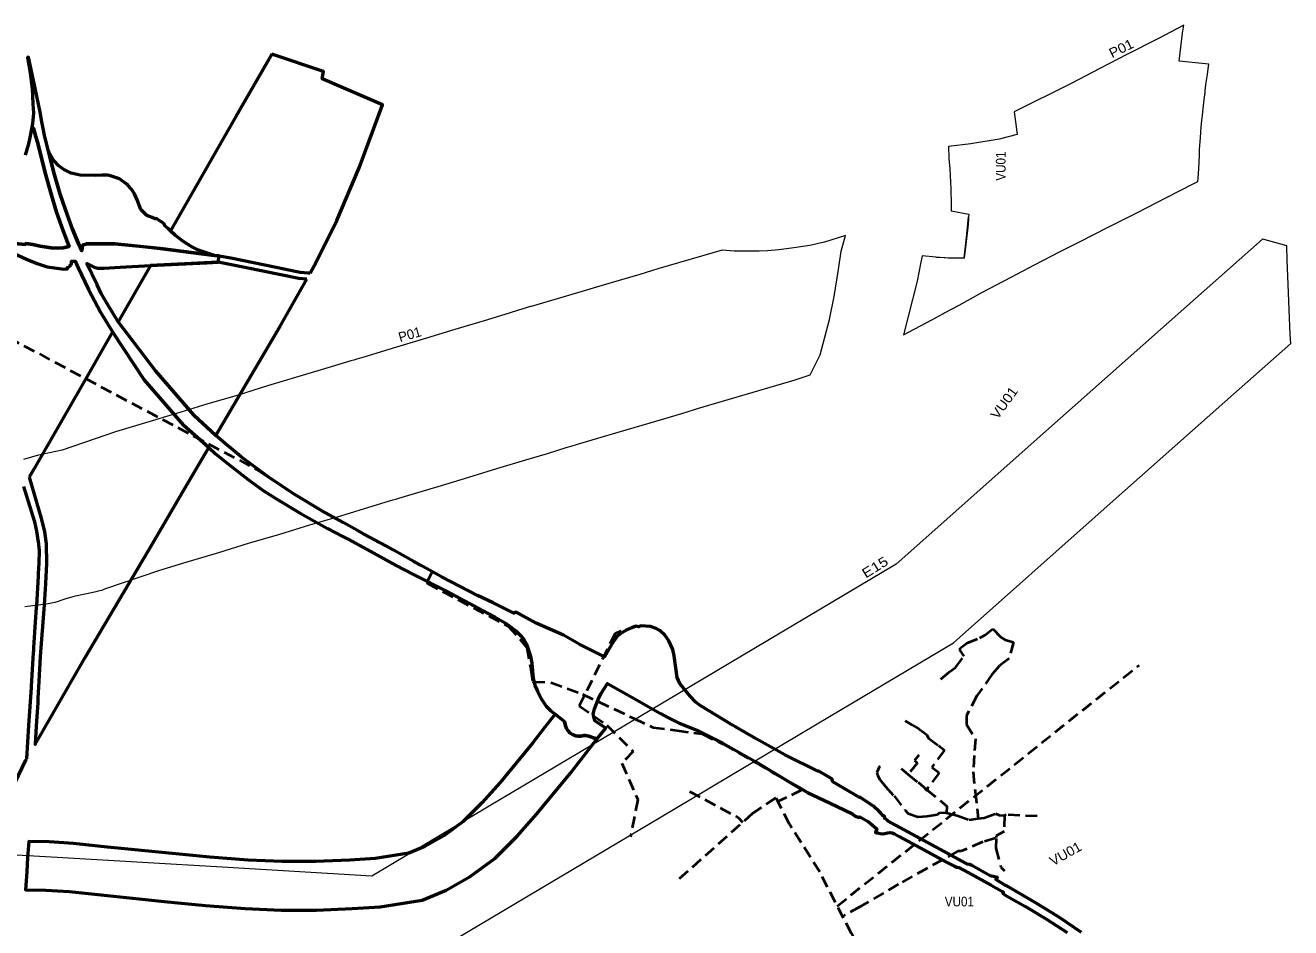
# Model space of a CAD drawing. Extents: x -650145 to -642675, y -1074338 to -1066803.
# Drawn here: x -647799 to -645184, y -1069131 to -1067267 of the extents above; entities that cross this region are included whole.
import ezdxf

# ---------------------------------------------------------------- set-up
doc = ezdxf.new("R2010")
doc.units = 0
doc.header["$LTSCALE"] = 8
doc.header["$PDMODE"] = 32
doc.header["$PDSIZE"] = 4
doc.linetypes.add('MEDIUM_DASHED', pattern=[4.5, 3, -1.5])
for name, color, linetype, lineweight in [('12', 7, 'MEDIUM_DASHED', 40), ('13', 7, 'MEDIUM_DASHED', 40), ('15', 7, 'Continuous', 13), ('20', 7, 'Continuous', 13), ('44', 7, 'Continuous', 53), ('45', 7, 'Continuous', 53)]:
    doc.layers.add(name, color=color, linetype=linetype, lineweight=lineweight)
for name, color, linetype in [('17', 7, 'Continuous'), ('2', 7, 'Continuous'), ('7', 7, 'Continuous')]:
    doc.layers.add(name, color=color, linetype=linetype)

msp = doc.modelspace()

# ---------------------------------------------------------------- linework, layer by layer
at = {"layer": '12'}
msp.add_line((-646121.289, -1069086.031), (-645497.437, -1068588.325), dxfattribs=at)
for points in [[(-646567.712, -1068518.211), (-646580.293, -1068523.244), (-646654.473, -1068672.619), (-646597.568, -1068712.249), (-646542.696, -1068767.122), (-646566.575, -1068791.001), (-646533.55, -1068865.689), (-646548.767, -1068942.794)], [(-646062.183, -1069574.695), (-646024.736, -1069561.612), (-645973.562, -1069340.254), (-646092.013, -1069143.037), (-646157.557, -1069015.41), (-646220.085, -1068916.892), (-646248.016, -1068862.258), (-646295.932, -1068894.5), (-646451.322, -1069032.874)], [(-646426.669, -1068849.138), (-646325.196, -1068903.916), (-646316.818, -1068913.099)]]:
    msp.add_lwpolyline(points, dxfattribs=at)
at = {"layer": '13'}
msp.add_line((-645981.259, -1068703.512), (-645967.385, -1068711.482), dxfattribs=at)
for points in [[(-648215.035, -1067709.37), (-647316.251, -1068186.868), (-647259.835, -1068225.099), (-647186.21, -1068269.45), (-646980.7, -1068383.53), (-646959.293, -1068395.4), (-646959.185, -1068396.415), (-646969.622, -1068417.689), (-646968.614, -1068419.427), (-646801.035, -1068508.24), (-646762.42, -1068551.731), (-646754.632, -1068597.002), (-646750.967, -1068622.409), (-646749.448, -1068623.2), (-646712.965, -1068624.297), (-646647.976, -1068648.366), (-646541.222, -1068698.652), (-646502.045, -1068716.94), (-646453.105, -1068723.49), (-646400.555, -1068730.38)], [(-645907.362, -1068617.782), (-645889.568, -1068602.563), (-645876.887, -1068593.676), (-645859.253, -1068569.608), (-645867.265, -1068558.084), (-645867.406, -1068553.24), (-645853.323, -1068543.361), (-645827.027, -1068531.945), (-645816.331, -1068526.326), (-645800.023, -1068513.497), (-645783.355, -1068530.492), (-645774.539, -1068535.947), (-645757.012, -1068540.689), (-645766.363, -1068574.93), (-645786.158, -1068590.096), (-645800.925, -1068607.466), (-645832.749, -1068651.725), (-645854.306, -1068692.564), (-645854.5, -1068711.115), (-645835.59, -1068740.909), (-645838.212, -1068775.032), (-645840.834, -1068809.155), (-645836.304, -1068849.486), (-645830.009, -1068905.531), (-645817.671, -1068904.145), (-645794.595, -1068895.246), (-645786.942, -1068898.462), (-645775.928, -1068898.705), (-645776.729, -1068932.361), (-645793.148, -1068940.923), (-645793.235, -1068944.604)], [(-646400.555, -1068730.38), (-646357.387, -1068751.896), (-646289.907, -1068789.892), (-646249.623, -1068813.511), (-646193.945, -1068846.371), (-646243.837, -1068870.431)], [(-645967.385, -1068711.482), (-645952.849, -1068719.994), (-645936.763, -1068731.758), (-645932.629, -1068739.558), (-645912.463, -1068754.396), (-645899.435, -1068764.348), (-645926.111, -1068799.268), (-645910.63, -1068811.261), (-645936.673, -1068845.097)], [(-645953.001, -1068774.241), (-645961.611, -1068785.748), (-645955.699, -1068790.171), (-645974.573, -1068814.129)], [(-646035.717, -1068796.972), (-646034.272, -1068798.019), (-646039.344, -1068810.269), (-646038.415, -1068815.963), (-646033.439, -1068824.717), (-646021.705, -1068839.115), (-646003.913, -1068858.499), (-645981.578, -1068887.109), (-645974.499, -1068895.164), (-645955.122, -1068901.554), (-645935.448, -1068900.633), (-645914.39, -1068896.88), (-645909.484, -1068892.742), (-645895.621, -1068893.663), (-645895.62, -1068893.657), (-645873.598, -1068899.269), (-645848.914, -1068907.655), (-645830.009, -1068905.531)], [(-645989.584, -1068801.939), (-645974.573, -1068814.129), (-645954.496, -1068830.434), (-645936.673, -1068845.097)], [(-645936.673, -1068845.097), (-645894.69, -1068879.637), (-645895.621, -1068893.657)], [(-645708.174, -1068900.605), (-645772.413, -1068897.59), (-645775.928, -1068898.705)], [(-645794.219, -1068945.883), (-645820.762, -1068953.606), (-645865.144, -1068972.751), (-645871.883, -1068972.89), (-645994.94, -1069041.005), (-646073.429, -1069086.912), (-646109.842, -1069107.217)], [(-645793.282, -1068946.603), (-645793.758, -1068966.676), (-645783.039, -1069005.778), (-645775.966, -1069013.04)]]:
    msp.add_lwpolyline(points, dxfattribs=at)
msp.add_point((-645936.673, -1068845.097), dxfattribs=at)
at = {"layer": '15'}
for points in [[(-645405.461, -1067266.956), (-645459.124, -1067294.842), (-645523.1, -1067327.464), (-645578.654, -1067356.15), (-645636.938, -1067386.16), (-645755.627, -1067445.619), (-645754.45, -1067456.07), (-645749.67, -1067492.54), (-645786.52, -1067502.4), (-645845.49, -1067511.66), (-645891.61, -1067517.46), (-645890.8, -1067542.09), (-645888.69, -1067563.35), (-645886.5, -1067604.41), (-645886.3, -1067638)], [(-645353.76, -1067347.31), (-645381.01, -1067344.47), (-645414.55, -1067340.98), (-645412.77, -1067323.6), (-645407.69, -1067283.25), (-645405.461, -1067266.956)], [(-645360.9, -1067401.05), (-645358.77, -1067385.3), (-645356.48, -1067368.37), (-645354.97, -1067357.16), (-645353.76, -1067347.31)], [(-645366.91, -1067452.72), (-645363.1, -1067419.95), (-645361.48, -1067406.06), (-645360.9, -1067401.05)], [(-645369.16, -1067476.7), (-645367.93, -1067463.58), (-645366.91, -1067452.72)], [(-645371.73, -1067507.06), (-645371.09, -1067499.49), (-645369.16, -1067476.7)], [(-645374.09, -1067562.75), (-645373, -1067535.51), (-645372.51, -1067523.27), (-645371.73, -1067507.06)], [(-645376.157, -1067589.286), (-645375.63, -1067582.48), (-645374.09, -1067562.75)], [(-645984.712, -1067905.99), (-645926.226, -1067874.994), (-645903.512, -1067862.929), (-645901.047, -1067861.609), (-645900.008, -1067861.056), (-645869.73, -1067844.967), (-645822.534, -1067819.103), (-645761.702, -1067787.243), (-645713.714, -1067761.995), (-645660.64, -1067734.415), (-645619.713, -1067713.557), (-645563.205, -1067684.762), (-645501.082, -1067653.64), (-645441.166, -1067622.79), (-645386.14, -1067594.376), (-645376.157, -1067589.286)], [(-645886.3, -1067638), (-645886.24, -1067648.47), (-645886.23, -1067649.44), (-645886.23, -1067649.94), (-645849.48, -1067657.36), (-645849.52, -1067657.86), (-645849.92, -1067662.49)], [(-645849.92, -1067662.49), (-645850.48, -1067668.94), (-645851.81, -1067684.35), (-645858.82, -1067747.99), (-645892.22, -1067747.76), (-645917.73, -1067746.17), (-645946.03, -1067743.35), (-645949.27, -1067759.64), (-645955.97, -1067795.26), (-645984.712, -1067905.99)], [(-645917.73, -1067746.17), (-645858.82, -1067747.99), (-645853.346, -1067698.291), (-645849.92, -1067662.49)], [(-646137.4, -1067874.3), (-646127.7, -1067827.4), (-646118.8, -1067771.3), (-646113, -1067733.4), (-646104.6, -1067701), (-646147.4, -1067714.8), (-646177.7, -1067721.6), (-646215.6, -1067727), (-646241.8, -1067731), (-646265.3, -1067733), (-646282.66, -1067733.1), (-646334.1, -1067733.4), (-646359.237, -1067731.258), (-646492.002, -1067769.967)], [(-646492.002, -1067769.967), (-646504.961, -1067774.022), (-646529.365, -1067781.499), (-646593.13, -1067800.524), (-646658.06, -1067819.479), (-646742.053, -1067843.994), (-646753.887, -1067847.445), (-646755.382, -1067847.819), (-646771.25, -1067852.794), (-646807.854, -1067864.206), (-646850.892, -1067877.156), (-646911.586, -1067895.218), (-646969.855, -1067913.144), (-647032.093, -1067931.929), (-647048.173, -1067936.726), (-647099.576, -1067952.077), (-647114.132, -1067956.487), (-647120.451, -1067958.402), (-647126.241, -1067960.149), (-647166.751, -1067972.422), (-647233.528, -1067992.581), (-647298.314, -1068011.911), (-647358.997, -1068030.632), (-647423.612, -1068049.375), (-647486.376, -1068068.781), (-647550.936, -1068088.002), (-647612.779, -1068106.747), (-647722.769, -1068144.312), (-647762.416, -1068152.578), (-647765.408, -1068153.202), (-647771.336, -1068154.692), (-647774.267, -1068155.557), (-647802.757, -1068163.967)], [(-646409.773, -1068058.581), (-646208.581, -1067999.266), (-646177.649, -1067988.892), (-646156.3, -1067947.3), (-646137.4, -1067874.3)], [(-647799.757, -1068467.7), (-647755.597, -1068461.87), (-647751.962, -1068461.39), (-647744.747, -1068460.076), (-647737.604, -1068458.41), (-647730.552, -1068456.398), (-647727.079, -1068455.221), (-647712.829, -1068450.391), (-647710.163, -1068449.487), (-647709.521, -1068449.242), (-647695.198, -1068445.014), (-647652.454, -1068436.102), (-647647.917, -1068435.156), (-647638.976, -1068432.708), (-647634.59, -1068431.21), (-647520.761, -1068392.333), (-647464.624, -1068375.318), (-647399.264, -1068355.859), (-647337.508, -1068336.765), (-647272.983, -1068318.048), (-647211.206, -1068298.989), (-647147.292, -1068279.919), (-647079.909, -1068259.578), (-647039.419, -1068247.311), (-647033.609, -1068245.558), (-647027.128, -1068243.593), (-647013.164, -1068239.363), (-646962.367, -1068224.194), (-646945.867, -1068219.271), (-646882.405, -1068200.116), (-646824.694, -1068182.362), (-646764.888, -1068164.564), (-646719.986, -1068151.054), (-646681.73, -1068139.126), (-646671.337, -1068135.868), (-646658.027, -1068131.986), (-646574, -1068107.461), (-646508.21, -1068088.256), (-646442.535, -1068068.661), (-646416.219, -1068060.598), (-646409.773, -1068058.581)]]:
    msp.add_lwpolyline(points, dxfattribs=at)
at = {"layer": '20'}
for points in [[(-646738.287, -1069051.902), (-646456.362, -1068884.319), (-646162.737, -1068709.771), (-645881.136, -1068542.25), (-645563.458, -1068260.279), (-645320.624, -1068044.744), (-645184.426, -1067923.894), (-645185.5, -1067905.76), (-645190.61, -1067785.41), (-645191.55, -1067752.42), (-645192.4, -1067722.74), (-645241.99, -1067708.63), (-645242.878, -1067708.378)], [(-645242.878, -1067708.378), (-645453.376, -1067895.156), (-645696.222, -1068110.701)], [(-645696.222, -1068110.701), (-645999.704, -1068380.07), (-646264.963, -1068537.869), (-646558.558, -1068712.401), (-646840.473, -1068879.978), (-647082.853, -1069024.029), (-647392.269, -1069006.02), (-647721.495, -1068986.72), (-648010.52, -1068969.88), (-648329.902, -1068951.251), (-648639.277, -1068933.111), (-648948.071, -1068915.071), (-649057.05, -1068908.69), (-649199.47, -1069030.73), (-649232.77, -1069060.44), (-649258.79, -1069091.17), (-649263.719, -1069096.97)], [(-649263.719, -1069096.97), (-648650.963, -1069132.769), (-648341.578, -1069150.909), (-648022.16, -1069169.54), (-647733.165, -1069186.38), (-647403.931, -1069205.68), (-647033.327, -1069227.251), (-646738.287, -1069051.902)]]:
    msp.add_lwpolyline(points, dxfattribs=at)
at = {"layer": '44'}
for points in [[(-647400.63, -1067756.19), (-647540.208, -1067762.876), (-647593.267, -1067855.425), (-647606.818, -1067879.061)], [(-647217.611, -1067791.149), (-647233.83, -1067789.69), (-647345.11, -1067767.28), (-647400.63, -1067756.19)], [(-647405.026, -1068113.904), (-647273.297, -1067889.981), (-647217.611, -1067791.149)], [(-647464.94, -1068215.752), (-647461.188, -1068209.373), (-647419.713, -1068138.871), (-647472.338, -1068093.096), (-647553.628, -1067999.427), (-647618.773, -1067899.914), (-647685.819, -1068016.861)], [(-647606.818, -1067879.061), (-647530.038, -1067980.839), (-647451.024, -1068071.886), (-647405.026, -1068113.904)], [(-647685.819, -1068016.861), (-647781.346, -1068183.485), (-647791.055, -1068200.507)], [(-647791.055, -1068200.507), (-647765.22, -1068287.94), (-647759.412, -1068313.436)], [(-647771.413, -1068334.626), (-647774.94, -1068311.47), (-647779.55, -1068292.23), (-647780.07, -1068290.53), (-647801.797, -1068219.34)], [(-647768.02, -1068570.36), (-647770.94, -1068622.47), (-647772.85, -1068656.41), (-647773.08, -1068660.57), (-647773.4, -1068665.71), (-647776.5, -1068714.8), (-647778.95, -1068752.433), (-647675.054, -1068572.919), (-647535.844, -1068336.279), (-647464.94, -1068215.752)], [(-647759.412, -1068313.436), (-647758.45, -1068317.66), (-647756.09, -1068337.61), (-647754.99, -1068378.21), (-647757.41, -1068419.98), (-647760.22, -1068463.96), (-647768.02, -1068570.36)], [(-647796.173, -1068782.191), (-647791.77, -1068713.23), (-647786.47, -1068634.37), (-647786.32, -1068632.19), (-647781.85, -1068562.97), (-647781.55, -1068558.38), (-647781.13, -1068551.88), (-647778.24, -1068499.95), (-647775.82, -1068469.74), (-647775.52, -1068464.97), (-647771.74, -1068404.5), (-647771.47, -1068400.07), (-647770.12, -1068377.5), (-647769.92, -1068352.1), (-647770.81, -1068340.29), (-647771.05, -1068337.01), (-647771.413, -1068334.626)], [(-647846.989, -1068896.545), (-647820.883, -1068832.117), (-647797.632, -1068784.713), (-647796.173, -1068782.191)]]:
    msp.add_lwpolyline(points, dxfattribs=at)
at = {"layer": '45'}
for points in [[(-647681.91, -1067732.74), (-647690.09, -1067716.05), (-647702.04, -1067686.86), (-647715.92, -1067648.12), (-647727.37, -1067614.33), (-647740.49, -1067568.67), (-647751.41, -1067526.58), (-647756.55, -1067505.32), (-647759.16, -1067494.01), (-647764.89, -1067466.64), (-647768.5, -1067446.04), (-647778.78, -1067397.1), (-647792.52, -1067332.74), (-647794.54, -1067333.14), (-647788.77, -1067365.03), (-647784.55, -1067398.01), (-647783.21, -1067429.237)], [(-647289.924, -1067326.309), (-647364.024, -1067455.561), (-647499.095, -1067691.163), (-647489.3, -1067700.07)], [(-647210.537, -1067778.594), (-647198.088, -1067756.5), (-647155.592, -1067670.17), (-647108.971, -1067561.55), (-647061.252, -1067430.908), (-647185.93, -1067377.38), (-647183.09, -1067362.16), (-647289.924, -1067326.309)], [(-647783.21, -1067429.237), (-647782.39, -1067448.34), (-647782.5, -1067455.11), (-647784.36, -1067469.6), (-647785.64, -1067477.02), (-647781.85, -1067479.19), (-647777.55, -1067496.95), (-647773.96, -1067508.48), (-647768.5, -1067529.75), (-647758.25, -1067571.79)], [(-647777.55, -1067496.95), (-647781.85, -1067479.19), (-647785.64, -1067477.02), (-647789.39, -1067498.84), (-647792.54, -1067511.85), (-647799.39, -1067535.48)], [(-647768.5, -1067529.75), (-647773.96, -1067508.48), (-647777.55, -1067496.95)], [(-647721.05, -1067691.73), (-647734.63, -1067652.57), (-647744.61, -1067617.96), (-647758.25, -1067571.79), (-647768.5, -1067529.75)], [(-647729.802, -1067557.462), (-647740.124, -1067546.265), (-647751.41, -1067526.58), (-647740.49, -1067568.67)], [(-647620.586, -1067578.478), (-647628.441, -1067576.759), (-647640.087, -1067576.306), (-647654.743, -1067576.996), (-647685.968, -1067576.68), (-647704.458, -1067572.034), (-647719.661, -1067564.884), (-647729.802, -1067557.462)], [(-647758.25, -1067571.79), (-647744.61, -1067617.96), (-647734.63, -1067652.57), (-647721.05, -1067691.73), (-647708.71, -1067723.99)], [(-647740.49, -1067568.67), (-647727.37, -1067614.33), (-647715.92, -1067648.12), (-647702.04, -1067686.86), (-647690.09, -1067716.05), (-647681.91, -1067732.74), (-647680.804, -1067720.745), (-647672, -1067718), (-647643, -1067718), (-647617.443, -1067718), (-647614, -1067718)], [(-647547.663, -1067659.519), (-647560.187, -1067647.458), (-647567.744, -1067627.24), (-647573.605, -1067614.951), (-647580.539, -1067604.432), (-647586.864, -1067597.411), (-647591.227, -1067593.613), (-647604.415, -1067584.047), (-647606.559, -1067583.309), (-647620.586, -1067578.478)], [(-647499.095, -1067691.163), (-647503.97, -1067686.73), (-647510.6, -1067680.86), (-647511.24, -1067677.53), (-647517.74, -1067672.85), (-647520.13, -1067671.13), (-647527.76, -1067665.65), (-647530.82, -1067666.65), (-647536.83, -1067663.64), (-647547.663, -1067659.519)], [(-647462.45, -1067719.84), (-647474.13, -1067711.81), (-647489.3, -1067700.07), (-647499.095, -1067691.163)], [(-647708.71, -1067723.99), (-647720.45, -1067726.49), (-647732.71, -1067727.02), (-647745.41, -1067726.6), (-647768.53, -1067722.82), (-647783.13, -1067719.68), (-647798.17, -1067717.58), (-647798.5, -1067719.67), (-647821.02, -1067717.33)], [(-647821.02, -1067717.33), (-647798.5, -1067719.67), (-647798.17, -1067717.58)], [(-647798.17, -1067717.58), (-647783.13, -1067719.68), (-647768.53, -1067722.82), (-647745.41, -1067726.6), (-647732.71, -1067727.02), (-647720.45, -1067726.49), (-647708.71, -1067723.99), (-647721.05, -1067691.73)], [(-647489.3, -1067700.07), (-647474.13, -1067711.81), (-647462.45, -1067719.84), (-647453.87, -1067724.97), (-647440.81, -1067731.38), (-647408.2, -1067742.37), (-647398.74, -1067743.15)], [(-647829.49, -1067734.58), (-647796.87, -1067750.25), (-647774.54, -1067758.68), (-647753.53, -1067765.58), (-647718.54, -1067770.6), (-647712.01, -1067769.63), (-647712.26, -1067767.28), (-647709.834, -1067766.324), (-647707.985, -1067765.133), (-647706.723, -1067763.999), (-647705.29, -1067762.21), (-647704.447, -1067760.707), (-647703.675, -1067758.576), (-647703.315, -1067756.406), (-647703.4, -1067753.8), (-647695.71, -1067753.9), (-647690.19, -1067766.37), (-647668.13, -1067812.76), (-647643.83, -1067859.13), (-647618.773, -1067899.914), (-647553.628, -1067999.427), (-647472.338, -1068093.096), (-647419.713, -1068138.871), (-647405.71, -1068151.74), (-647372.38, -1068179.01), (-647337.74, -1068205.67), (-647307.39, -1068227.44), (-647281.64, -1068244.34), (-647230.83, -1068274.93), (-647174.56, -1068306.35), (-647142.788, -1068322.462), (-647130.29, -1068328.8), (-647079.16, -1068357.01), (-647032.91, -1068382.51), (-646997.06, -1068401.37), (-646927.06, -1068436.66), (-646854.18, -1068475.8), (-646828.2, -1068489.61), (-646807.82, -1068501.17), (-646799.79, -1068506.39), (-646785.34, -1068517.77), (-646775.44, -1068527.74), (-646768.95, -1068535.8), (-646763.1, -1068545.18), (-646754.92, -1068569.81), (-646752.59, -1068584.55), (-646749.35, -1068615.18), (-646746.32, -1068630.23)], [(-646653.21, -1068545.58), (-646653.21, -1068545.58), (-646686.84, -1068526.89), (-646743.69, -1068501.76), (-646785.05, -1068479.12), (-646789.49, -1068481.31), (-646832.29, -1068460.04), (-646864.48, -1068444.64), (-646938.95, -1068405.8), (-647002.71, -1068371.09), (-647053.75, -1068342.11), (-647099.2, -1068318.27), (-647112.813, -1068310.564), (-647142.41, -1068293.81), (-647186.26, -1068269.45), (-647243.39, -1068235.26), (-647295.47, -1068201.09), (-647347.74, -1068162.54), (-647353.81, -1068157.67), (-647385.13, -1068131.51), (-647405.026, -1068113.904), (-647451.024, -1068071.886), (-647530.038, -1067980.839), (-647606.818, -1067879.061), (-647628.396, -1067844.048), (-647642.29, -1067820.76), (-647650.8, -1067803.28), (-647672.05, -1067758.98), (-647656.469, -1067766.309), (-647649.22, -1067768.38), (-647635.758, -1067768.38), (-647602.885, -1067766.486), (-647540.208, -1067762.876), (-647423.683, -1067757.294), (-647400.63, -1067756.19), (-647398.74, -1067743.15), (-647408.2, -1067742.37), (-647520.145, -1067727.879), (-647614, -1067718), (-647617.443, -1067718), (-647643, -1067718), (-647672, -1067718), (-647680.804, -1067720.745), (-647681.91, -1067732.74)], [(-647614, -1067718), (-647557, -1067724), (-647520.145, -1067727.879), (-647408.2, -1067742.37), (-647440.81, -1067731.38)], [(-647440.81, -1067731.38), (-647453.87, -1067724.97), (-647462.45, -1067719.84)], [(-647398.74, -1067743.15), (-647374.55, -1067747.34), (-647280.78, -1067766.44), (-647237.91, -1067775.18), (-647231.17, -1067776.55), (-647213.92, -1067778.26), (-647210.537, -1067778.594)], [(-645616.63, -1069140.8), (-645662.44, -1069109.89), (-645694.447, -1069089.98), (-645713.61, -1069078.06), (-645770.04, -1069045.34), (-645773.38, -1069043.46), (-645793.638, -1069031.021), (-645790.53, -1069027.19), (-645805.16, -1069023.52), (-645843.56, -1069002.41), (-645848.18, -1069000.48), (-645852.91, -1068999.62), (-645856.26, -1068997.79), (-645892.77, -1068977.86), (-645933.28, -1068955.74), (-645975.31, -1068932.8), (-646017.55, -1068909.75), (-646017.39, -1068908.42), (-646023.56, -1068905.05), (-646023.13, -1068903.12), (-646023.92, -1068900.73), (-646025.57, -1068899.39), (-646028.18, -1068898.89), (-646031.31, -1068894.32), (-646034.65, -1068891.12), (-646046.48, -1068879.92), (-646074.78, -1068861.51), (-646075.56, -1068861.95), (-646130.68, -1068829.21), (-646132.62, -1068823.54), (-646159.1, -1068807.43), (-646161.45, -1068807.54), (-646229.44, -1068773.53), (-646288.59, -1068740.88), (-646331.26, -1068716.25), (-646337.93, -1068712.4), (-646404.83, -1068671.52), (-646413.45, -1068664.71), (-646425.11, -1068652.37), (-646446.54, -1068626.14), (-646451.82, -1068614.31), (-646458.03, -1068569.26), (-646461.14, -1068556.34), (-646469.51, -1068538.15), (-646477.41, -1068526.45), (-646487.92, -1068516.87), (-646495.416, -1068512.888), (-646507.4, -1068508.45), (-646528.18, -1068507.58), (-646531.9, -1068509.25), (-646537.71, -1068508.16), (-646545.57, -1068511.42), (-646556.22, -1068515.84), (-646559.72, -1068517.29), (-646569.61, -1068524.1), (-646577.07, -1068530.2), (-646587.28, -1068545.28), (-646599.75, -1068566.49), (-646602.21, -1068571.5), (-646653.21, -1068545.58), (-646653.21, -1068545.58)], [(-646746.32, -1068630.23), (-646740.91, -1068642.34), (-646732.25, -1068659.06), (-646722.6, -1068673.11)], [(-646722.6, -1068673.11), (-646712.93, -1068683), (-646684.7, -1068704.95), (-646682.98, -1068714.07), (-646680.88, -1068719.28), (-646678.08, -1068723.7), (-646673.16, -1068728.69), (-646667.17, -1068732.38), (-646661.5, -1068734.35), (-646656.47, -1068735.13), (-646651.21, -1068734.99), (-646645.18, -1068733.91), (-646642.04, -1068733.74), (-646634.37, -1068735.27), (-646622.62, -1068739.32), (-646617.991, -1068741.503), (-646599.51, -1068718.755), (-646622.01, -1068703.3), (-646625.35, -1068689.7), (-646622.68, -1068678.75), (-646615.19, -1068659.11), (-646609.7, -1068647.84), (-646596.28, -1068626.52), (-646545.73, -1068654.81), (-646486.23, -1068688.54), (-646470.225, -1068697.579), (-646448.02, -1068707.99), (-646411.3, -1068723.11), (-646357.87, -1068749.64), (-646288.37, -1068789.04), (-646214.92, -1068832.85), (-646195.52, -1068843.92), (-646182.57, -1068851.3), (-646137.23, -1068872.6), (-646089.63, -1068895.5), (-646084.1, -1068900.51), (-646076.09, -1068903.48), (-646074.51, -1068901.9), (-646057.13, -1068911.62), (-646039.84, -1068926.67), (-646042.5, -1068933.91), (-646040.65, -1068934.59), (-646037.5, -1068934.7), (-646032.61, -1068936.1), (-646027.69, -1068936.6), (-646022.77, -1068936.12), (-646017.6, -1068934.89), (-646012.64, -1068934.34), (-646007.7, -1068935.18), (-646002.95, -1068936.95), (-645993.5, -1068942.1), (-645940.77, -1068970.74), (-645896.91, -1068994.75), (-645879.17, -1069004.02), (-645874.49, -1069005.73), (-645869.83, -1069006.45), (-645850.79, -1069016.84), (-645803.29, -1069042.92), (-645781.12, -1069055.29), (-645777.73, -1069057.2), (-645779.49, -1069059.92), (-645773.29, -1069063.99), (-645732.65, -1069086.82), (-645688.87, -1069113.44), (-645646.08, -1069140.37)]]:
    msp.add_lwpolyline(points, dxfattribs=at)
msp.add_lwpolyline([(-646934.465, -1068940.759), (-646973.61, -1068963.135), (-647006.63, -1068977.08), (-647076.422, -1068988.18), (-647128.674, -1068991.167), (-647199.672, -1068994.255), (-647268.348, -1068994.255), (-647338.816, -1068991.19), (-647417.895, -1068984.986), (-647502.412, -1068977.157), (-647629.424, -1068964.608), (-647699.561, -1068956.635), (-647749.978, -1068953.416), (-647792.01, -1068952.442), (-647794.21, -1068986.12), (-647796.13, -1069015.57), (-647798.631, -1069052.508), (-647756.441, -1069053.207), (-647708.401, -1069056.275), (-647511.94, -1069076.703), (-647426.417, -1069084.624), (-647344.902, -1069091.02), (-647270.522, -1069094.255), (-647197.498, -1069094.255), (-647123.648, -1069091.043), (-647065.688, -1069087.73), (-646978.92, -1069073.93), (-646929.186, -1069052.925), (-646880.163, -1069024.903), (-646829.104, -1068987.917), (-646782.784, -1068941.581), (-646741.85, -1068895.719), (-646673.05, -1068812.491), (-646618.655, -1068742.359), (-646617.991, -1068741.503), (-646622.62, -1068739.32), (-646634.37, -1068735.27), (-646642.04, -1068733.74), (-646645.18, -1068733.91), (-646651.21, -1068734.99), (-646656.47, -1068735.13), (-646661.5, -1068734.35), (-646667.17, -1068732.38), (-646673.16, -1068728.69), (-646678.08, -1068723.7), (-646680.88, -1068719.28), (-646682.98, -1068714.07), (-646684.7, -1068704.95), (-646704.316, -1068689.698), (-646725.374, -1068716.786), (-646751.116, -1068749.975), (-646817.718, -1068830.545), (-646855.506, -1068872.883), (-646894.206, -1068911.595)], close=True, dxfattribs=at)

# ---------------------------------------------------------------- texts
at = {"layer": '17', "width": 1.1}
msp.add_text('P01', height=20, rotation=26.08, dxfattribs=at).set_placement((-645553.682, -1067335.106))
at = {"layer": '17'}
msp.add_text('P01', height=20, rotation=15.899, dxfattribs=at).set_placement((-647024.707, -1067921.547))
at = {"layer": '2'}
for rotation, width, p in [(54.217, 1.1, (-645789.911, -1068082.457)), (29.327, 1.05, (-645675.485, -1069004.004))]:
    msp.add_text('VU01', height=20, rotation=rotation, dxfattribs=dict(at, width=width)).set_placement(p)
at = {"layer": '2', "width": 0.9}
msp.add_text('VU01', height=20, dxfattribs=at).set_placement((-645899.102, -1069086.768))
at = {"layer": '20', "width": 1.2}
msp.add_text('E15', height=20, rotation=31.922, dxfattribs=at).set_placement((-646062.368, -1068409.739))
at = {"layer": '7', "width": 0.9}
msp.add_text('VU01', height=20, rotation=89.972, dxfattribs=at).set_placement((-645773.6, -1067587.836))

doc.saveas('drawing.dxf')
